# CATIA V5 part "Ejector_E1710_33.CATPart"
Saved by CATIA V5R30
Part number: Vyhazovac_7x160_9
Nomenclature: E1710/7x160
Description: MEUSBURGER
Property "Material": "1.221"
Publications: "__DrillHole", "Base"
Bounding box of the stored display mesh (mm): x -5.992 to 5.992, y -5.992 to 5.992, z 0 to 156.5
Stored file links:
  E:\Bakalarka\Model\Forma_v7\Ejector_E1710_33.CATPart
  E:\dev\MoldDesign\intel_a\startup\components\MoldCatalog\Ejector\Meusburger\Ejector_E1710\TableE1710.txt
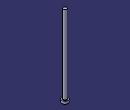
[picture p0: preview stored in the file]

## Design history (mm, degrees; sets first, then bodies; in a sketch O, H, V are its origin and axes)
Parameters
  Ref = "E1710/7x160" {design table}
  D1 = 7 mm {design table}
  D3 = 12 mm {design table}
  L = 160 mm {design table}
  L3 = 5 mm {design table}
  R = 0.5 mm {design table}
  k_d3 = 13 mm {design table}
  k_d1 = 7.2 mm {design table}
  k_F = 0.5 mm {design table}
  kl = 17 mm {design table}
  Mat = "1.221" {design table}
  HeatTreat = "ISO6751" {design table}
  Offset_Parting = 10 mm
  Anti_Rotation = "Normal"
  Anti_Rotation_D = 4 mm
  Anti_Rotation_D_Icut = 4 mm
  Add_Length_L = 1.3377 mm
  Add_Length_D3 = 0 mm
  SupplierRef = "Meusburger 2017"
  BmpRef = "F_MldEjectorD1"
  DrillHole_Length = 225 mm
  ValidationTest = false
  Anti_Rotation_D_min = 4 mm {= OffSet_D1 /2}
  Anti_Rotation_D_max = 5.925 mm {= D3/2-0.075mm}
  Anti_Rotation_D_ref = 4 mm {= Anti_Rotation_D}
  Anti_Rotation_D_Icut_ref = 4 mm {= Anti_Rotation_D_Icut}
  Anti_Rotation_Ref_Icut = 2.3246 mm
  Offset_L = 20 mm
  D = 7 mm {= D1}
  OffSet_D1 = 8 mm {= D1+2*R}
  OffSet_D3 = 13 mm {= D3+1mm}
  XG_Split = 100 mm
  YG_Split = 25 mm
  ZG_Split = -198 mm
  DirX_Split = 0 mm
  DirY_Split = 0 mm
  DirZ_Split = 1 mm
Set1 "BaseBody"
  Point1 "Base": (0, 0, 0)
  Plane1: type Offset, RefPlane xy-plane, Offset 225 {= DrillHole_Length}, reversed
  Sketch1 "Sketch.2" on xy-plane, origin (0, 0, 0), H (1, 0, 0), V (0, 1, 0)
    point P1 (-0.46, 1.1623)
    point P2 (0.46, 1.1623)
    construction line L1 (-0.46, 1.1623) -> (0.46, 1.1623)
    point P3 (0.46, -1.1623)
    line L2 (0.46, -1.1623) -> (0.46, 1.1623)
    point P4 (-0.46, -1.1623)
    construction line L3 (0.46, -1.1623) -> (-0.46, -1.1623)
    line L4 (-0.46, 1.1623) -> (-0.46, -1.1623)
    point P5 (-0.21, 1.1623)
    arc A1 centre (-0.21, 1.1623) radius 0.25 from (-0.21, 1.4123) to (-0.46, 1.1623) ccw
    point P7 (0.21, 1.1623)
    point P8 (0.21, 1.4123)
    arc A2 centre (0.21, 1.1623) radius 0.25 from (0.46, 1.1623) to (0.21, 1.4123) ccw
    line L5 (-0.21, 1.4123) -> (0.21, 1.4123)
    point P9 (-0.46, -1.1623)
    arc A3 centre (-0.21, -1.1623) radius 0.25 from (-0.46, -1.1623) to (-0.21, -1.4123) ccw
    point P11 (0.21, -1.4123)
    line L6 (-0.21, -1.4123) -> (0.21, -1.4123)
    point P12 (0.46, -1.1623)
    arc A4 centre (0.21, -1.1623) radius 0.25 from (0.21, -1.4123) to (0.46, -1.1623) ccw
    point P14 (-0.46, 1.1623)
    point P15 (-0.46, -1.1623)
    point P16 (0.46, 1.1623)
    point P17 (0.46, -1.1623)
    reference projected circle E1 centre (0, 0) radius 1.25 from edge [face of Shaft1 from Sketch2.L3 | face of Shaft1 from Sketch2.L4]
    reference projected circle E2 centre (0, 0) radius 1.25 from edge [face of Shaft1 from Sketch2.L3 | face of Shaft1 from Sketch2.L4]
    reference projected circle E3 centre (0, 0) radius 1.25 from edge [face of Shaft1 from Sketch2.L3 | face of Shaft1 from Sketch2.L4]
    reference projected circle E4 centre (0, 0) radius 1.25 from edge [face of Shaft1 from Sketch2.L3 | face of Shaft1 from Sketch2.L4]
    point P18 (-0.46, -1.1623)
    point P19 (-0.21, -1.4123)
    point P20 (0.21, -1.4123)
    point P21 (0.46, -1.1623)
    point P22 (-0.21, -1.4123)
    point P23 (0.21, -1.4123)
    distance P14 P15 = 2.3246 (reference)
    distance P16 P17 = 2.3246 (reference)
    distance L1 P14 = 0 (reference)
    radius A1 = 3.5
    distance L4 V = 4.01
    distance L2 V = 5.935
    distance L5 L6 = 12
    horizontal: L1 H, L3 H, L5 H
    vertical: L2 V, L4 V
    coincidence: P5 L1, P7 L1, P3 P12, P14 L4, P15 L4, P16 L2, P17 L2, P14 E1, P15 E2, P16 E3, P17 E4, P3 P21, P4 P18, P20 P23, P19 P22
    tangency: A1 L4, A2 L2, A2 L5, A1 L5
    symmetry: P1 P9 H, A1 A3 H, P8 P11 H, L5 L6 H, P2 P12 H, A2 A4 H
  DatumSurface1
Body1 "PartBody" (main body)
  Sketch2 "Sketch.1" on zx-plane, origin (0, 0, 0), H (-1, 0, 0), V (0, 0, 1)
    point P1 (0, 160)
    line L1 (3.5, 160) -> (0, 160)
    line L2 (3.5, 5) -> (3.5, 160)
    line L3 (6, 5) -> (3.5, 5)
    line L4 (6, 0) -> (6, 5)
    point P5 (0, 0)
    line L5 (0, 0) -> (6, 0)
    point P6 (0, 160)
    axis line L6 (0, 160) -> (0, 0)
    point P7 (0, 0)
    point P8 (3.5, 5)
    point P9 (3.5, 5)
    line L7 (0, 160) -> (0, 0)
    distance L5 L3 = 5 {= L3}
    distance L5 L1 = 160 {= L}
    distance L2 L6 = 3.5 {= D1 /2}
    distance L4 L6 = 6 {= D3 /2}
    coincidence: L6 P5, P1 L6, L5 H, L6 V, P7 O, P6 P1, P8 P9
    vertical: L2 V, L7 V
    horizontal: L1 H
  Shaft1 "Shaft.1": profile Sketch2, axis Sketch2.L6, angle 360
  Pocket1 "Pocket.1": profile Sketch1, direction (0, 0, 1), length 6, outer side, deactivated
  Pocket2 "Pocket.2": profile Sketch1, direction (0, 0, 1), length 6, outer side, deactivated
  Fillet1: radius 0.5 {= R}, on edge [face of Shaft1 from Sketch2.L2 | face of Shaft1 from Sketch2.L3]
  Pocket3: profile face of Shaft1 from Sketch2.L1, direction along face of Shaft1 from Sketch2.L1 reversed, up to face of DatumSurface1
Body2 "__DrillHole"
  Sketch3 "Sketch.3" on face of Shaft1, origin (0, 0, 0), H (1, 0, 0), V (0, -1, 0)
    point P1 (0, 0)
    reference projected point E1 (0, 0) from Point1
    coincidence: E1 P1
  Hole1 "Hole.1": placed by Sketch3, at (0, 0, 0) direction (0, 0, 1), diameter 8 {= OffSet_D1}, depth 140 {= L-Offset_L}
  Sketch4 "Sketch.4" on face of Shaft1, origin (0, 0, 0), H (1, 0, 0), V (0, -1, 0)
    point P1 (0, 0)
    reference projected point E1 (0, 0) from Point1
    coincidence: E1 P1
  Hole2 "Hole.2": placed by Sketch4, at (0, 0, 0) direction (0, 0, 1), diameter 7 {= D1}, depth 160 {= L}
  Sketch5 "Sketch.5" on face of Shaft1 from Sketch2.L3, origin (0, 0, 5), H (1, 0, 0), V (0, 1, 0)
    point P1 (0, 0)
    reference projected point E1 (0, 0) from Point1
    coincidence: E1 P1
  Hole3 "Hole.3": placed by Sketch5, at (0, 0, 5) direction (0, 0, -1), diameter 13 {= OffSet_D3}, depth 230 {= L3 +DrillHole_Length}
  Chamfer1: length 0.5 {= k_F}, angle 45, on edge [face of Hole1 | face of Hole3]
  Body3 "__Body.1"
    Pocket4 "Pocket.3": profile Sketch1, direction (0, 0, -1), length 225, opposite side length 5, deactivated
  Assemble1: tool Body3
  Chamfer2: length 0.5 {= k_F}, angle 45, on edge [start face of Pocket4 | face of Hole1], deactivated
  Body4 "__Body.2"
    Pocket5 "Pocket.4": profile Sketch1, direction (0, 0, -1), length 225, opposite side length 5, deactivated
  Assemble2: tool Body4
  Chamfer3: length 0.5 {= k_F}, angle 45, on edge [start face of Pocket5 | face of Hole1], deactivated
Relations
  design table "TableE1710", configuration 278, drives Ref, D1, D3, L, L3, R, k_d3, k_d1, k_F, kl, Mat, HeatTreat
  Offset_L = 20mm (deactivated)
  rule "Cut_Head_rule":
    let sketch_cut (length)
    let PartBody_Pocket_Sketch (Boolean)
    let I_PartBody_Pocket (Boolean)
    let D_PartBody_Pocket (Boolean)
    let N_DrillHole_Hole (Boolean)
    let N_DrillHole_Hole_Sketch (Boolean)
    let I_DrillHole_Pocket (Boolean)
    let D_DrillHole_Pocket (Boolean)
    /* --------------------------------------------------------------------------------------*/
    if Anti_Rotation =="Normal"
    {
    	sketch_cut=Anti_Rotation_D_max
    	PartBody_Pocket_Sketch = false
    	I_PartBody_Pocket = false
    	D_PartBody_Pocket = false
    	N_DrillHole_Hole = true
    	N_DrillHole_Hole_Sketch = true
    	I_DrillHole_Pocket = false
    	D_DrillHole_Pocket = false
    	Chamfer1.Activity= true
    	Chamfer2.Activity= false
    	Chamfer3.Activity= false
    }
    if Anti_Rotation == "I_Cut"
    {
    	sketch_cut=Anti_Rotation_D_Icut_ref
    	PartBody_Pocket_Sketch = true
    	I_PartBody_Pocket = true
    	D_PartBody_Pocket = false
    	N_DrillHole_Hole = false
    	N_DrillHole_Hole_Sketch = false
    	I_DrillHole_Pocket = true
    	D_DrillHole_Pocket = false
    	Chamfer1.Activity= false
    	Chamfer2.Activity= true
    	Chamfer3.Activity= false
    }
    if Anti_Rotation =="D_Cut"
    {
    	sketch_cut=Anti_Rotation_D_max
    	PartBody_Pocket_Sketch = true
    	I_PartBody_Pocket = false
    	D_PartBody_Pocket = true
    	N_DrillHole_Hole = false
    	N_DrillHole_Hole_Sketch = false
    	I_DrillHole_Pocket = false
    	D_DrillHole_Pocket = true
    	Chamfer1.Activity= false
    	Chamfer2.Activity= false
    	Chamfer3.Activity= true
    }
    /* --------------------------------------------------------------------------------------*/
    Sketch1.distance(L2 V) = sketch_cut+0.01mm
    Sketch1.distance(L4 V) =Anti_Rotation_D_ref+0.01mm
    Sketch1.radius(A1) =D/2
    Pocket4.FirstLimit.Depth = DrillHole_Length
    Pocket5.FirstLimit.Depth = DrillHole_Length
    Pocket1.FirstLimit.Depth = L3+1mm
    Pocket2.FirstLimit.Depth = L3+1mm
    Pocket4.SecondLimit.Depth = L3
    Pocket5.SecondLimit.Depth =L3
    Pocket1.Activity = I_PartBody_Pocket
    Pocket2.Activity = D_PartBody_Pocket
    Sketch1.Activity =PartBody_Pocket_Sketch
    Hole3.Activity= N_DrillHole_Hole
    Sketch5.Activity = N_DrillHole_Hole_Sketch
    Pocket4.Activity = I_DrillHole_Pocket
    Pocket5.Activity  = D_DrillHole_Pocket
  rule "Anti_Rotation_Icut_constrain":
    let Ref1(length)
    let Ref2(length)
    let Ref3(length)
    let Diam1(length)
    let Diam2(length)
    let Add_Length_Lmin (length)
    Ref1=Sketch1.distance(P14 P15)
    Ref2=Sketch1.distance(P16 P17)
    Diam1=D
    Diam2=D3
    /* --------------------------------------------------------------------*/
    if Ref1 >Ref2
    	Anti_Rotation_Ref_Icut = Ref1
    else
    	Anti_Rotation_Ref_Icut  =Ref2
    Add_Length_D3 .InferiorRange=Anti_Rotation_Ref_Icut /2+Diam1/2 -Diam2/2
    if Add_Length_D3 .InferiorRange<0mm
    	Add_Length_D3 .InferiorRange=0mm
    if ValidationTest == "true"
    	Ref3   = 2*Add_Length_L +Anti_Rotation_Ref_Icut  +2*Diam1/2
    else
    	Ref3  =Diam2+2*Add_Length_D3
    if Ref3 <Diam2
    {
    	Ref3 =Diam2
    }
    /* --------------------------------------------------------------------*/
    Sketch1.distance(L5 L6) = Ref3
    Add_Length_L .InferiorRange=Diam2/2-Anti_Rotation_Ref_Icut/2-Diam1/2
    Add_Length_Lmin=Diam2/2-Anti_Rotation_Ref_Icut/2-Diam1/2
    if Add_Length_Lmin<0mm
    	Add_Length_L .InferiorRange=0mm
    else
    	Add_Length_L .InferiorRange=Add_Length_Lmin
